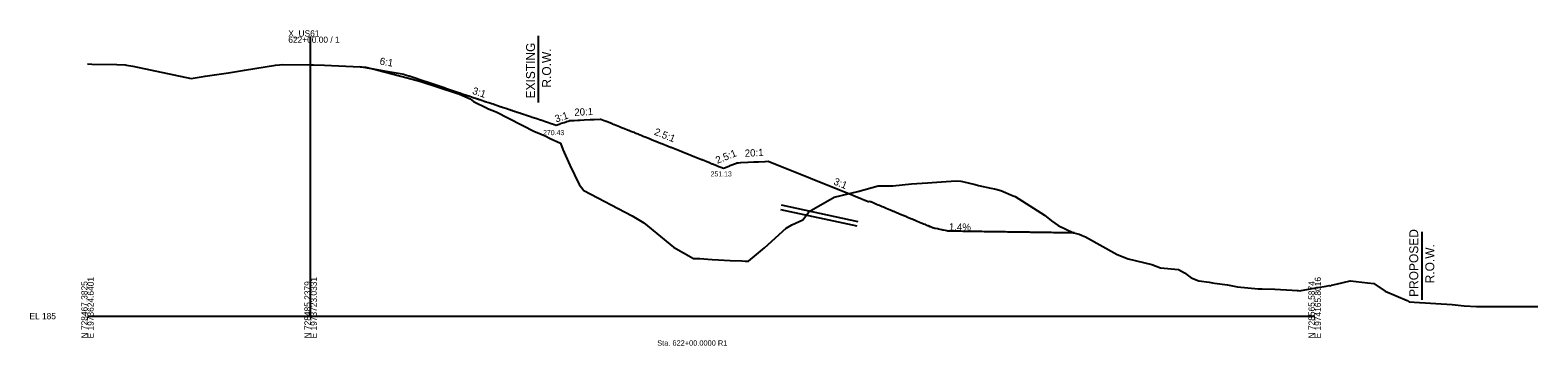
# Model space of a CAD drawing. Extents: x -26 to 1629, y -25 to 9635.
# Drawn here: x -26 to 650, y 4987 to 5128 of the extents above; entities that cross this region are included whole.
import ezdxf

# ---------------------------------------------------------------- set-up
doc = ezdxf.new("R2010")
doc.units = 0
for name, color, linetype in [('Default', 7, 'Continuous'), ('Draft_XS_Grid', 7, 'Continuous'), ('Draft_XS_Text', 7, 'Continuous'), ('DTM CONTOURS_MAJOR', 7, 'Continuous'), ('DTM_X_GROUND', 7, 'Continuous'), ('XS_CELL', 7, 'Continuous'), ('XS_P_DRAINAGE', 7, 'Continuous'), ('XS_P_GROUND', 7, 'Continuous'), ('XS_P_ROW', 7, 'Continuous'), ('XS_P_TX_DCH', 7, 'Continuous'), ('XS_P_TX_FS_BS', 7, 'Continuous'), ('XS_X_ROW', 7, 'Continuous')]:
    doc.layers.add(name, color=color, linetype=linetype)

msp = doc.modelspace()

# ---------------------------------------------------------------- linework, layer by layer
at = {"layer": 'DTM_X_GROUND'}
msp.add_lwpolyline([(0, 5112.78), (1.97, 5112.73), (13.2, 5112.47), (16.89, 5112.3), (17.55, 5112.27), (20.31, 5111.7), (46.48, 5106.23), (52.8, 5107.24), (56.95, 5107.9), (63.22, 5108.85), (70.38, 5110.04), (84.31, 5112.28), (86.12, 5112.42), (87.35, 5112.52), (100.12, 5112.41), (101.23, 5112.4), (106.16, 5112.17), (122.26, 5111.42), (124.73, 5111.27), (125.32, 5111.23), (130.08, 5110.01), (143.22, 5106.52), (149.43, 5104.84), (165.85, 5099.52), (166.45, 5099.32), (166.71, 5099.18), (171.57, 5097.17), (173.04, 5095.89), (179.17, 5092.92), (179.28, 5092.87), (183.1, 5091.34), (200.41, 5082.62), (201.5, 5082.12), (205.13, 5080.54), (207.41, 5079.43), (212.02, 5077.34), (212.98, 5074.48), (216.22, 5067.46), (220.31, 5058.87), (222.47, 5056.14), (244.14, 5044.89), (249.36, 5041.69), (262.58, 5030.78), (271.65, 5025.8), (274.42, 5025.7), (278.09, 5025.44), (280.03, 5025.29), (282.77, 5025.21), (288.03, 5024.89), (293.22, 5024.65), (294.68, 5024.56), (296.21, 5024.51), (302.57, 5029.8), (303.39, 5030.46), (303.43, 5030.49), (303.47, 5030.53), (313.09, 5039.39), (315.61, 5040.79), (320.64, 5043.08), (323.5, 5046.83), (334.59, 5053.12), (334.66, 5053.13), (345.27, 5055.67), (354.39, 5058.31), (360.94, 5058.19), (369.29, 5059.14), (376.49, 5059.64), (384.89, 5060.2), (389.32, 5060.41), (391.42, 5060.34), (392.15, 5060.26), (397.87, 5058.81), (399.3, 5058.47), (404.85, 5057.2), (406.49, 5056.87), (409.37, 5056.17), (414.91, 5053.8), (415.75, 5053.46), (428.87, 5045.07), (432.05, 5042.56), (435.08, 5040.54), (441.95, 5037.22), (443.3, 5036.98), (444.39, 5036.69), (445.41, 5036.12), (445.8, 5036.07), (447.22, 5035.38), (461.52, 5027.54), (466.37, 5025.56), (476.95, 5023.06), (480.86, 5021.59), (488.97, 5020.78), (491.67, 5019.3), (494.62, 5017.06), (498.03, 5015.82), (502.66, 5015.12), (504.26, 5014.82), (505.11, 5014.69), (510.87, 5013.96), (515.45, 5013.13), (524.65, 5012.21), (525.79, 5012.19), (526.46, 5012.16), (532.12, 5012), (539.91, 5011.61), (542.18, 5011.45), (542.7, 5011.43), (543.76, 5011.36), (543.99, 5011.39), (551.37, 5012.81), (555.14, 5013.45), (556.52, 5013.7), (557.16, 5013.46), (557.51, 5013.88), (559.59, 5014.27), (565.85, 5015.76), (566.07, 5015.73), (573.59, 5014.89), (576.47, 5014.59), (581.57, 5011.08), (591.44, 5007.04), (592.4, 5006.42), (594.61, 5006.26), (611.63, 5005.13), (616.94, 5004.56), (622.54, 5004.35), (631.66, 5004.3), (636.74, 5004.29), (639.22, 5004.32), (646.1, 5004.32), (650, 5004.33)], dxfattribs=at)
at = {"layer": 'XS_CELL'}
for p, q in [((100, 5000), (100, 5125)), ((0, 5000), (100, 5000)), ((100, 5000), (550, 5000))]:
    msp.add_line(p, q, dxfattribs=at)
at = {"layer": 'XS_P_DRAINAGE'}
for p, q in [((310.52, 5047.73), (344.78, 5040.34)), ((310.94, 5049.69), (345.2, 5042.3))]:
    msp.add_line(p, q, dxfattribs=at)
at = {"layer": 'XS_P_GROUND'}
for points in [[(142, 5108.1), (134.8, 5109.3), (128.21, 5110.39), (122, 5111.43)], [(142, 5108.1), (144.04, 5107.42), (144.19, 5107.37), (151.59, 5104.9), (151.78, 5104.84), (160.23, 5102.02), (160.45, 5101.95), (166.72, 5099.85), (166.9, 5099.8), (168.36, 5099.31), (168.4, 5099.3), (169.86, 5098.81), (169.9, 5098.8), (171.35, 5098.31), (171.4, 5098.3), (172.83, 5097.82), (172.9, 5097.8), (174.27, 5097.34), (174.4, 5097.3), (174.54, 5097.25), (174.75, 5097.18), (174.96, 5097.11), (175.59, 5096.9), (175.9, 5096.8), (176.63, 5096.55), (177.14, 5096.38), (177.4, 5096.3), (178.29, 5096), (178.68, 5095.87), (178.9, 5095.8), (179.13, 5095.72), (179.81, 5095.49), (180.29, 5095.33), (180.39, 5095.3), (180.8, 5095.16), (180.94, 5095.11), (181.14, 5095.05), (181.68, 5094.87), (181.74, 5094.85), (182.38, 5094.63), (182.48, 5094.6), (182.51, 5094.59), (183.32, 5094.32), (184.14, 5094.05), (184.44, 5093.95), (185.01, 5093.76), (185.45, 5093.61), (185.72, 5093.52), (185.85, 5093.48), (186.01, 5093.42), (186.36, 5093.31), (187.54, 5092.92), (187.88, 5092.8), (187.92, 5092.79), (188.19, 5092.7), (188.28, 5092.67), (188.39, 5092.63), (188.52, 5092.59), (188.71, 5092.53), (189.1, 5092.39), (189.23, 5092.35), (189.92, 5092.12), (190.19, 5092.03), (190.75, 5091.85), (190.83, 5091.82), (191.36, 5091.64), (191.69, 5091.53), (191.79, 5091.5), (192.53, 5091.25), (192.65, 5091.21), (194.24, 5090.68), (194.38, 5090.64), (196.03, 5090.08), (196.1, 5090.06), (196.95, 5089.78), (196.97, 5089.77), (197.01, 5089.76), (198.71, 5089.19), (198.77, 5089.17), (201.32, 5088.32), (201.36, 5088.31), (203.06, 5087.74), (203.12, 5087.72), (204, 5087.43), (204.81, 5087.16), (205.66, 5086.88), (205.69, 5086.87), (205.75, 5086.84), (208.32, 5085.99), (208.35, 5085.98), (209.2, 5085.69), (209.25, 5085.68), (210, 5085.43), (210.97, 5085.75), (211.83, 5086.04), (211.85, 5086.05), (211.9, 5086.06), (213.62, 5086.64), (213.64, 5086.64), (214.51, 5086.93), (214.71, 5087), (214.83, 5087.04), (215.4, 5087.23), (215.84, 5087.38), (216, 5087.43), (216.28, 5087.44), (216.29, 5087.44), (217.89, 5087.52), (218.07, 5087.53), (219.77, 5087.62), (219.85, 5087.62), (220.72, 5087.66), (220.75, 5087.67), (220.79, 5087.67), (222.54, 5087.76), (222.6, 5087.76), (225.23, 5087.89), (225.28, 5087.89), (227.03, 5087.98), (227.1, 5087.98), (229.75, 5088.12), (229.78, 5088.12), (230, 5088.13), (230.01, 5088.13), (231.56, 5087.51), (231.58, 5087.5), (232.47, 5087.14), (232.53, 5087.12), (235.2, 5086.05), (235.22, 5086.04), (236.11, 5085.69), (236.17, 5085.66), (238.41, 5084.76), (238.44, 5084.75), (239.32, 5084.4), (239.33, 5084.4), (239.77, 5084.22), (239.79, 5084.21), (240.69, 5083.85), (240.72, 5083.84), (242.06, 5083.31), (242.07, 5083.3), (242.53, 5083.12), (242.55, 5083.11), (243.45, 5082.75), (243.48, 5082.74), (244.8, 5082.21), (244.81, 5082.2), (245.29, 5082.01), (245.33, 5082), (246.64, 5081.47), (246.65, 5081.47), (247.14, 5081.27), (247.17, 5081.26), (248.07, 5080.9), (248.11, 5080.89), (249.4, 5080.37), (249.41, 5080.36), (249.93, 5080.16), (249.94, 5080.15), (250.32, 5080), (250.37, 5079.98), (252.17, 5079.26), (252.18, 5079.26), (252.72, 5079.04), (252.77, 5079.02), (254.59, 5078.29), (254.65, 5078.27), (256.82, 5077.4), (256.83, 5077.4), (257.4, 5077.17), (257.47, 5077.14), (260.22, 5076.04), (261.33, 5075.6), (261.55, 5075.51), (275.23, 5070.04), (275.38, 5069.98), (275.45, 5069.95), (278.25, 5068.83), (278.4, 5068.77), (279, 5068.53), (279.21, 5068.45), (280.01, 5068.12), (280.17, 5068.06), (282.02, 5067.32), (282.09, 5067.29), (282.25, 5067.23), (285, 5066.13), (285.95, 5066.51), (287.8, 5067.25), (287.88, 5067.28), (287.95, 5067.31), (290.8, 5068.45), (290.85, 5068.47), (291, 5068.53), (291.77, 5068.57), (292.7, 5068.61), (292.75, 5068.62), (292.83, 5068.62), (296.08, 5068.78), (296.14, 5068.79), (298.63, 5068.91), (298.68, 5068.91), (300.6, 5069.01), (300.67, 5069.01), (303.57, 5069.16), (303.64, 5069.16), (305, 5069.23), (343.03, 5054.02), (344, 5053.63), (349.85, 5051.29), (350, 5051.23), (350.46, 5051.41)], [(350.46, 5051.41), (350.95, 5051.21), (351.03, 5051.17), (352.11, 5050.72), (352.35, 5050.62), (353.27, 5050.24), (353.64, 5050.09), (354.43, 5049.76), (354.91, 5049.55), (355.58, 5049.27), (356.17, 5049.03), (356.74, 5048.79), (357.41, 5048.51), (357.9, 5048.31), (358.64, 5048), (359.06, 5047.82), (359.87, 5047.49), (360.21, 5047.34), (361.09, 5046.98), (361.37, 5046.86), (362.3, 5046.47), (362.53, 5046.37), (363.5, 5045.97), (363.69, 5045.89), (364.7, 5045.47), (364.85, 5045.41), (365.9, 5044.97), (366, 5044.92), (367.09, 5044.47), (367.16, 5044.44), (368.28, 5043.97), (368.32, 5043.96), (369.47, 5043.48), (369.48, 5043.47), (369.61, 5043.42), (370.53, 5043.04), (370.63, 5042.99), (371.56, 5042.6), (371.79, 5042.51), (372.6, 5042.17), (372.95, 5042.03), (373.64, 5041.74), (374.11, 5041.54), (374.67, 5041.31), (375.26, 5041.06), (375.71, 5040.87), (376.42, 5040.58), (376.75, 5040.44), (377.58, 5040.09), (377.78, 5040.01), (378.74, 5039.61), (378.82, 5039.57), (379.53, 5039.28)], [(385.49, 5037.99), (385.22, 5038.05), (385.2, 5038.05), (385.16, 5038.06), (384.52, 5038.2), (383.71, 5038.37), (383.37, 5038.45), (382.86, 5038.56), (382.21, 5038.7), (381.42, 5038.87), (381.05, 5038.95), (379.98, 5039.18), (379.89, 5039.2), (379.83, 5039.21), (379.53, 5039.28)], [(442.34, 5037.17), (441.25, 5037.18), (441.23, 5037.18), (440.09, 5037.2), (440.04, 5037.2), (438.93, 5037.22), (438.85, 5037.22), (437.77, 5037.23), (437.67, 5037.24), (436.62, 5037.25), (436.48, 5037.25), (435.46, 5037.27), (435.29, 5037.27), (434.3, 5037.28), (434.18, 5037.29), (433.59, 5037.3), (433.5, 5037.3), (433.14, 5037.3), (432.92, 5037.3), (431.99, 5037.32), (431.73, 5037.32), (430.83, 5037.33), (430.53, 5037.34), (429.67, 5037.35), (429.33, 5037.36), (428.51, 5037.37), (428.14, 5037.37), (427.36, 5037.39), (426.94, 5037.39), (426.2, 5037.4), (425.75, 5037.41), (425.04, 5037.42), (424.55, 5037.43), (423.88, 5037.44), (423.36, 5037.44), (422.73, 5037.45), (422.17, 5037.46), (421.57, 5037.47), (420.98, 5037.48), (420.41, 5037.49), (419.79, 5037.49), (419.25, 5037.5), (418.6, 5037.51), (418.09, 5037.52), (417.41, 5037.53), (416.94, 5037.54), (416.22, 5037.55), (415.78, 5037.55), (415.03, 5037.56), (414.62, 5037.57), (414.44, 5037.57), (414.35, 5037.57), (414.19, 5037.58), (414.11, 5037.58), (413.95, 5037.58), (413.87, 5037.58), (413.59, 5037.58), (413.46, 5037.59), (412.66, 5037.6), (412.31, 5037.6), (411.47, 5037.61), (411.15, 5037.62), (410.29, 5037.63), (409.99, 5037.64), (409.1, 5037.65), (408.83, 5037.65), (407.92, 5037.67), (407.68, 5037.67), (406.74, 5037.68), (406.52, 5037.69), (405.56, 5037.7), (405.36, 5037.7), (404.6, 5037.71), (404.47, 5037.72), (404.24, 5037.72), (404.2, 5037.72), (403.2, 5037.73), (403.05, 5037.74), (402.01, 5037.75), (401.89, 5037.75), (400.83, 5037.77), (400.73, 5037.77), (399.65, 5037.79), (399.57, 5037.79), (398.47, 5037.8), (398.42, 5037.8), (397.29, 5037.82), (397.26, 5037.82), (396.11, 5037.84), (396.1, 5037.84), (395.41, 5037.85), (395.07, 5037.85), (395.07, 5037.85), (394.94, 5037.85), (394.88, 5037.85), (393.79, 5037.87), (393.57, 5037.87), (392.63, 5037.89), (392.26, 5037.89), (391.47, 5037.9), (390.95, 5037.91), (390.31, 5037.92), (389.64, 5037.93), (389.15, 5037.94), (388.33, 5037.95), (388, 5037.95), (387.02, 5037.97), (386.84, 5037.97), (385.71, 5037.99), (385.68, 5037.99), (385.49, 5037.99)]]:
    msp.add_lwpolyline(points, dxfattribs=at)
at = {"layer": 'XS_P_ROW'}
msp.add_line((598, 5037.64), (598, 5007.32), dxfattribs=at)
at = {"layer": 'XS_X_ROW'}
msp.add_line((202, 5125.39), (202, 5095.5), dxfattribs=at)

# ---------------------------------------------------------------- texts
at = {"layer": 'Default'}
for p in [(141.96, 5108.04), (385.45, 5037.93)]:
    msp.add_text('X', height=0.12, dxfattribs=at).set_placement(p)
at = {"layer": 'Draft_XS_Grid'}
msp.add_text('-', height=0.0001, dxfattribs=at).set_placement((0, 5000))
at = {"layer": 'Draft_XS_Text'}
msp.add_text('Sta. 622+00.0000 R1', height=2.4, dxfattribs=at).set_placement((255.34, 4986.75))
at = {"layer": 'DTM CONTOURS_MAJOR'}
for p in [(121.96, 5111.37), (141.96, 5108.04), (229.96, 5088.07), (203.96, 5087.37), (209.96, 5085.37), (215.96, 5087.37), (278.96, 5068.47), (290.96, 5068.47), (304.96, 5069.17), (284.96, 5066.07), (343.96, 5053.57), (349.96, 5051.17), (362.72, 5052.78), (379.49, 5039.22), (395.37, 5037.79)]:
    msp.add_text('X', height=0.12, dxfattribs=at).set_placement(p)
at = {"layer": 'XS_CELL'}
for s, p in [('X_US61', (90, 5125)), ('622+00.00 / 1', (90, 5122.2)), ('EL 185', (-26, 4998.6))]:
    msp.add_text(s, height=2.8, dxfattribs=at).set_placement(p)
for s, p in [('N 728467.3825', (0, 4990)), ('E 1973624.6401', (2.8, 4990)), ('N 728485.2379', (100, 4990)), ('E 1973723.0331', (102.8, 4990)), ('N 728565.5874', (550, 4990)), ('E 1974165.8016', (552.8, 4990))]:
    msp.add_text(s, height=2.8, rotation=90, dxfattribs=at).set_placement(p)
at = {"layer": 'XS_P_ROW'}
for s, p in [('PROPOSED', (596.37, 5008.57)), ('R.O.W.', (603.57, 5014.64))]:
    msp.add_text(s, height=4, rotation=90, dxfattribs=at).set_placement(p)
at = {"layer": 'XS_P_TX_DCH'}
for s, p in [('270.43', (204.18, 5080.91)), ('251.13', (279.26, 5062.47))]:
    msp.add_text(s, height=2.25, dxfattribs=at).set_placement(p)
at = {"layer": 'XS_P_TX_FS_BS'}
for s, rotation, p in [('6:1', 350.53766, (130.78, 5112.51)), ('3:1', 341.56507, (172.22, 5099.45)), ('3:1', 18.43493, (210.03, 5086.54)), ('20:1', 2.86241, (218.25, 5089.52)), ('2.5:1', 338.19859, (253.7, 5081.22)), ('20:1', 2.86241, (294.63, 5071.2)), ('2.5:1', 21.80141, (282.26, 5068.05)), ('3:1', 338.19859, (334.09, 5058.97)), ('1.4%', 359.17115, (386.03, 5038.28))]:
    msp.add_text(s, height=3.24, rotation=rotation, dxfattribs=at).set_placement(p)
at = {"layer": 'XS_X_ROW'}
for s, p in [('EXISTING', (200.56, 5097.33)), ('R.O.W.', (207.76, 5102.17))]:
    msp.add_text(s, height=4, rotation=90, dxfattribs=at).set_placement(p)

doc.saveas('drawing.dxf')
